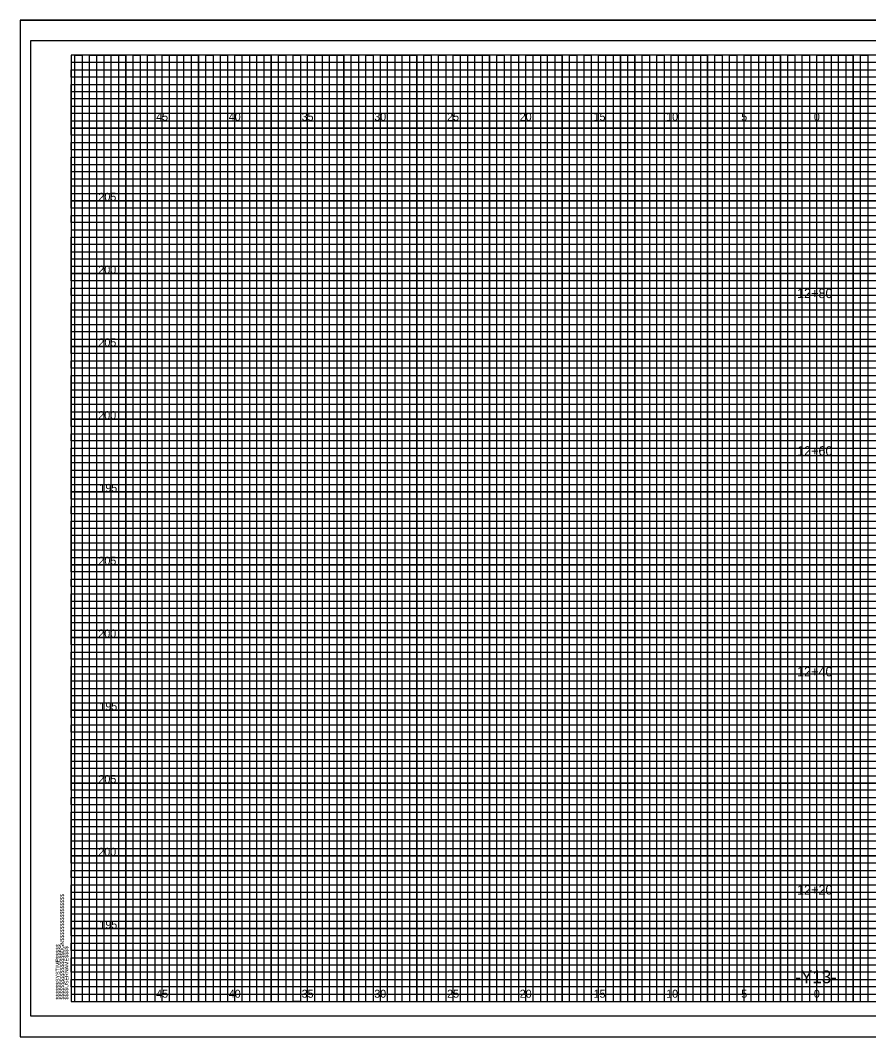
# Model space of a CAD drawing. Extents: x -4 to 103, y -2 to 209.
# Drawn here: x -3.5 to 54.8, y 68.4 to 138.2 of the extents above; entities that cross this region are included whole.
import ezdxf

# ---------------------------------------------------------------- set-up
doc = ezdxf.new("R2010")
doc.units = 0
for name, color, linetype in [('Exist XS Ground Line', 7, 'Continuous'), ('Old_Level_10', 7, 'Continuous'), ('Old_Level_16', 7, 'Continuous'), ('Old_Level_3', 7, 'Continuous'), ('Old_Level_5', 7, 'Continuous'), ('Old_Level_8', 7, 'Continuous'), ('Prop XS Finish Grade Earthwork', 7, 'Continuous'), ('Prop XS Finish Grade Pavement', 7, 'Continuous'), ('Prop XS Pvmt Edge Slope', 7, 'Continuous'), ('Prop XS SE Text', 7, 'Continuous'), ('Prop XS Suitable Common Exc Shape', 7, 'Continuous')]:
    doc.layers.add(name, color=color, linetype=linetype)

msp = doc.modelspace()

# ---------------------------------------------------------------- linework, layer by layer
at = {"layer": 'Exist XS Ground Line'}
msp.add_lwpolyline([(103, 136.825), (-2.8, 136.825), (-2.8, 69.825), (103, 69.825)], close=True, dxfattribs=at)
at = {"layer": 'Old_Level_10'}
for p, q in [((1.25, 70.825), (1.25, 135.825)), ((3.75, 70.825), (3.75, 135.825)), ((6.25, 70.825), (6.25, 135.825)), ((8.75, 70.825), (8.75, 135.825)), ((11.25, 70.825), (11.25, 135.825)), ((13.75, 70.825), (13.75, 135.825)), ((16.25, 70.825), (16.25, 135.825)), ((18.75, 70.825), (18.75, 135.825)), ((21.25, 70.825), (21.25, 135.825)), ((23.75, 70.825), (23.75, 135.825)), ((26.25, 70.825), (26.25, 135.825)), ((28.75, 70.825), (28.75, 135.825)), ((31.25, 70.825), (31.25, 135.825)), ((33.75, 70.825), (33.75, 135.825)), ((36.25, 70.825), (36.25, 135.825)), ((38.75, 70.825), (38.75, 135.825)), ((41.25, 70.825), (41.25, 135.825)), ((43.75, 70.825), (43.75, 135.825)), ((46.25, 70.825), (46.25, 135.825)), ((48.75, 70.825), (48.75, 135.825)), ((51.25, 70.825), (51.25, 135.825)), ((53.75, 70.825), (53.75, 135.825)), ((0, 133.325), (74.25, 133.325)), ((0, 130.825), (102.5, 130.825)), ((0, 128.325), (102.5, 128.325)), ((0, 125.825), (102.5, 125.825)), ((0, 123.325), (102.5, 123.325)), ((0, 120.825), (102.5, 120.825)), ((0, 118.325), (102.5, 118.325)), ((0, 115.825), (102.5, 115.825)), ((0, 113.325), (102.5, 113.325)), ((0, 110.825), (102.5, 110.825)), ((0, 108.325), (102.5, 108.325)), ((0, 105.825), (102.5, 105.825)), ((0, 103.325), (102.5, 103.325)), ((0, 100.825), (102.5, 100.825)), ((0, 98.325), (102.5, 98.325)), ((0, 95.825), (102.5, 95.825)), ((0, 93.325), (102.5, 93.325)), ((0, 90.825), (102.5, 90.825)), ((0, 88.325), (102.5, 88.325)), ((0, 85.825), (102.5, 85.825)), ((0, 83.325), (102.5, 83.325)), ((0, 80.825), (102.5, 80.825)), ((0, 78.325), (102.5, 78.325)), ((0, 75.825), (102.5, 75.825)), ((0, 73.325), (102.5, 73.325))]:
    msp.add_line(p, q, dxfattribs=at)
at = {"layer": 'Old_Level_3'}
for p, q in [((-3.5, 138.225), (103.4, 138.225)), ((-3.5, 138.225), (-3.5, 68.4)), ((-3.5, 68.4), (103.4, 68.4))]:
    msp.add_line(p, q, dxfattribs=at)
at = {"layer": 'Old_Level_5'}
msp.add_lwpolyline([(103.4, 138.225), (-3.5, 138.225), (-3.5, 68.4), (103.4, 68.4)], close=True, dxfattribs=at)
at = {"layer": 'Old_Level_8'}
for points in [[(1.25, 70.825), (1.25, 135.825), (3.75, 135.825), (3.75, 70.825), (6.25, 70.825), (6.25, 135.825), (8.75, 135.825), (8.75, 70.825), (11.25, 70.825), (11.25, 135.825), (13.75, 135.825), (13.75, 70.825), (16.25, 70.825), (16.25, 135.825), (18.75, 135.825), (18.75, 70.825), (21.25, 70.825), (21.25, 135.825), (23.75, 135.825), (23.75, 70.825), (26.25, 70.825), (26.25, 135.825), (28.75, 135.825), (28.75, 70.825), (31.25, 70.825), (31.25, 135.825), (33.75, 135.825), (33.75, 70.825), (36.25, 70.825), (36.25, 135.825), (38.75, 135.825), (38.75, 70.825), (41.25, 70.825), (41.25, 135.825), (43.75, 135.825), (43.75, 70.825), (46.25, 70.825), (46.25, 135.825), (48.75, 135.825), (48.75, 70.825), (51.25, 70.825), (51.25, 135.825), (53.75, 135.825), (53.75, 70.825)], [(102.5, 130.825), (0, 130.825), (0, 133.325), (74.25, 133.325)], [(102.5, 125.825), (0, 125.825), (0, 128.325), (102.5, 128.325)], [(102.5, 120.825), (0, 120.825), (0, 123.325), (102.5, 123.325)], [(102.5, 115.825), (0, 115.825), (0, 118.325), (102.5, 118.325)], [(102.5, 110.825), (0, 110.825), (0, 113.325), (102.5, 113.325)], [(102.5, 105.825), (0, 105.825), (0, 108.325), (102.5, 108.325)], [(102.5, 100.825), (0, 100.825), (0, 103.325), (102.5, 103.325)], [(102.5, 95.825), (0, 95.825), (0, 98.325), (102.5, 98.325)], [(102.5, 90.825), (0, 90.825), (0, 93.325), (102.5, 93.325)], [(102.5, 85.825), (0, 85.825), (0, 88.325), (102.5, 88.325)], [(102.5, 80.825), (0, 80.825), (0, 83.325), (102.5, 83.325)], [(102.5, 75.825), (0, 75.825), (0, 78.325), (102.5, 78.325)], [(0, 73.325), (102.5, 73.325)]]:
    msp.add_lwpolyline(points, dxfattribs=at)
at = {"layer": 'Prop XS Finish Grade Earthwork'}
for points in [[(0.25, 70.825), (0.25, 135.825), (0.75, 135.825), (0.75, 70.825), (1.75, 70.825), (1.75, 135.825), (2.25, 135.825), (2.25, 70.825), (2.75, 70.825), (2.75, 135.825), (3.25, 135.825), (3.25, 70.825), (4.25, 70.825), (4.25, 135.825), (4.75, 135.825), (4.75, 70.825), (5.25, 70.825), (5.25, 135.825), (5.75, 135.825), (5.75, 70.825), (6.75, 70.825), (6.75, 135.825), (7.25, 135.825), (7.25, 70.825), (7.75, 70.825), (7.75, 135.825), (8.25, 135.825), (8.25, 70.825), (9.25, 70.825), (9.25, 135.825), (9.75, 135.825), (9.75, 70.825), (10.25, 70.825), (10.25, 135.825), (10.75, 135.825), (10.75, 70.825), (11.75, 70.825), (11.75, 135.825), (12.25, 135.825), (12.25, 70.825), (12.75, 70.825), (12.75, 135.825), (13.25, 135.825), (13.25, 70.825), (14.25, 70.825), (14.25, 135.825), (14.75, 135.825), (14.75, 70.825), (15.75, 70.825), (15.25, 70.825), (15.25, 135.825), (15.75, 135.825), (15.75, 70.825), (16.75, 70.825), (16.75, 135.825), (17.25, 135.825), (17.25, 70.825), (17.75, 70.825), (17.75, 135.825), (18.25, 135.825), (18.25, 70.825), (19.25, 70.825), (19.25, 135.825), (19.75, 135.825), (19.75, 70.825), (20.25, 70.825), (20.25, 135.825), (20.75, 135.825), (20.75, 70.825), (21.75, 70.825), (21.75, 135.825), (22.25, 135.825), (22.25, 70.825), (22.75, 70.825), (22.75, 135.825), (23.25, 135.825), (23.25, 70.825), (24.25, 70.825), (24.25, 135.825), (24.75, 135.825), (24.75, 70.825), (25.25, 70.825), (25.25, 135.825), (25.75, 135.825), (25.75, 70.825), (26.75, 70.825), (26.75, 135.825), (27.25, 135.825), (27.25, 70.825), (27.75, 70.825), (27.75, 135.825), (28.25, 135.825), (28.25, 70.825), (29.25, 70.825), (29.25, 135.825), (29.75, 135.825), (29.75, 70.825), (30.25, 70.825), (30.25, 135.825), (30.75, 135.825), (30.75, 70.825)], [(30.75, 70.825), (31.75, 70.825), (31.75, 135.825), (32.25, 135.825), (32.25, 70.825), (32.75, 70.825), (32.75, 135.825), (33.25, 135.825), (33.25, 70.825), (34.25, 70.825), (34.25, 135.825), (34.75, 135.825), (34.75, 70.825), (35.25, 70.825), (35.25, 135.825), (35.75, 135.825), (35.75, 70.825), (36.75, 70.825), (36.75, 135.825), (37.25, 135.825), (37.25, 70.825), (37.75, 70.825), (37.75, 135.825), (37.75, 70.825)], [(38.25, 135.825), (38.25, 70.825), (39.25, 70.825), (39.25, 135.825), (39.75, 135.825), (39.75, 70.825), (40.25, 70.825), (40.25, 135.825), (40.75, 135.825), (40.75, 70.825), (41.75, 70.825), (41.75, 135.825), (42.25, 135.825), (42.25, 70.825), (42.75, 70.825), (42.75, 135.825), (43.25, 135.825), (43.25, 70.825), (43.75, 70.825), (44.25, 70.825), (44.25, 135.825), (44.75, 135.825), (44.75, 70.825), (45.25, 70.825), (45.25, 135.825), (45.75, 135.825), (45.75, 70.825), (46.75, 70.825), (46.75, 135.825), (47.25, 135.825), (47.25, 70.825), (47.75, 70.825), (47.75, 135.825), (48.25, 135.825), (48.25, 70.825), (49.25, 70.825), (49.25, 135.825), (49.75, 135.825), (49.75, 70.825), (50.25, 70.825), (50.25, 135.825), (50.75, 135.825), (50.75, 70.825), (51.75, 70.825), (51.75, 135.825), (52.25, 135.825), (52.25, 70.825), (52.75, 70.825), (52.75, 135.825), (53.25, 135.825), (53.25, 70.825), (54.25, 70.825), (54.25, 135.825), (54.75, 135.825), (54.75, 70.825), (55.25, 70.825)], [(0, 132.825), (0, 133.825), (74.25, 133.825), (74.25, 134.325), (0, 134.325), (0, 134.825), (74.25, 134.825), (74.25, 135.325), (0, 135.325)], [(102.5, 132.825), (0, 132.825)], [(102.5, 131.825), (0, 131.825), (0, 132.325), (102.5, 132.325)], [(102.5, 130.325), (0, 130.325), (0, 131.325), (102.5, 131.325)], [(102.5, 129.325), (0, 129.325), (0, 129.825), (102.5, 129.825)], [(102.5, 127.825), (0, 127.825), (0, 128.825), (102.5, 128.825)], [(102.5, 126.825), (0, 126.825), (0, 127.325), (102.5, 127.325)], [(102.5, 125.325), (0, 125.325), (0, 126.325), (102.5, 126.325)], [(102.5, 124.325), (0, 124.325), (0, 124.825), (102.5, 124.825)], [(0, 123.825), (102.5, 123.825)], [(102.5, 122.825), (0, 122.825)], [(102.5, 121.825), (0, 121.825), (0, 122.325), (102.5, 122.325)], [(102.5, 120.325), (0, 120.325), (0, 121.325), (102.5, 121.325)], [(102.5, 119.325), (0, 119.325), (0, 119.825), (102.5, 119.825)], [(102.5, 117.825), (0, 117.825), (0, 118.825), (102.5, 118.825)], [(102.5, 116.825), (0, 116.825), (0, 117.325), (102.5, 117.325)], [(102.5, 115.325), (0, 115.325), (0, 116.325), (102.5, 116.325)], [(102.5, 114.325), (0, 114.325), (0, 114.825), (102.5, 114.825)], [(102.5, 112.825), (0, 112.825), (0, 113.825), (102.5, 113.825)], [(102.5, 111.825), (0, 111.825), (0, 112.325), (102.5, 112.325)], [(102.5, 110.325), (0, 110.325), (0, 111.325), (102.5, 111.325)], [(102.5, 109.325), (0, 109.325), (0, 109.825), (102.5, 109.825)], [(102.5, 107.825), (0, 107.825), (0, 108.825), (102.5, 108.825)], [(102.5, 106.825), (0, 106.825), (0, 107.325), (102.5, 107.325)], [(102.5, 105.325), (0, 105.325), (0, 106.325), (102.5, 106.325)], [(102.5, 104.325), (0, 104.325), (0, 104.825), (102.5, 104.825)], [(102.5, 102.825), (0, 102.825), (0, 103.825), (102.5, 103.825)], [(102.5, 101.825), (0, 101.825), (0, 102.325)], [(0, 102.325), (102.5, 102.325)], [(102.5, 100.325), (0, 100.325), (0, 101.325), (102.5, 101.325)], [(102.5, 99.325), (0, 99.325), (0, 99.825), (102.5, 99.825)], [(102.5, 97.825), (0, 97.825), (0, 98.825), (102.5, 98.825)], [(102.5, 96.825), (0, 96.825), (0, 97.325), (102.5, 97.325)], [(102.5, 95.325), (0, 95.325), (0, 96.325), (102.5, 96.325)], [(102.5, 94.325), (0, 94.325), (0, 94.825), (102.5, 94.825)], [(102.5, 92.825), (0, 92.825), (0, 93.825), (102.5, 93.825)], [(102.5, 91.825), (0, 91.825), (0, 92.325), (102.5, 92.325)], [(102.5, 90.325), (0, 90.325), (0, 91.325), (102.5, 91.325)], [(102.5, 89.325), (0, 89.325), (0, 89.825), (102.5, 89.825)], [(102.5, 87.825), (0, 87.825), (0, 88.825), (102.5, 88.825)], [(102.5, 86.825), (0, 86.825), (0, 87.325), (102.5, 87.325)], [(102.5, 85.325), (0, 85.325), (0, 86.325), (102.5, 86.325)], [(102.5, 84.325), (0, 84.325), (0, 84.825), (102.5, 84.825)], [(102.5, 82.825), (0, 82.825), (0, 83.825), (102.5, 83.825)], [(102.5, 81.825), (0, 81.825), (0, 82.325), (102.5, 82.325)], [(102.5, 80.325), (0, 80.325), (0, 81.325), (102.5, 81.325)], [(102.5, 79.325), (0, 79.325), (0, 79.825), (102.5, 79.825)], [(102.5, 77.825), (0, 77.825), (0, 78.825), (102.5, 78.825)], [(102.5, 76.825), (0, 76.825), (0, 77.325), (102.5, 77.325)], [(102.5, 75.325), (0, 75.325), (0, 76.325), (102.5, 76.325)], [(102.5, 74.325), (0, 74.325), (0, 74.825), (102.5, 74.825)], [(102.5, 72.825), (0, 72.825), (0, 73.825), (102.5, 73.825)], [(102.5, 71.825), (0, 71.825), (0, 72.325), (102.5, 72.325)], [(0, 71.325), (102.5, 71.325)]]:
    msp.add_lwpolyline(points, dxfattribs=at)
at = {"layer": 'Prop XS SE Text'}
msp.add_lwpolyline([(102.5, 135.825), (0, 135.825), (0, 70.825), (102.5, 70.825)], close=True, dxfattribs=at)

# ---------------------------------------------------------------- texts
at = {"layer": 'Old_Level_16'}
for s, p in [('45', (5.84, 131.325)), ('40', (10.831, 131.325)), ('35', (15.84, 131.325)), ('30', (20.831, 131.325)), ('25', (25.84, 131.325)), ('20', (30.831, 131.325)), ('15', (35.906, 131.325)), ('10', (40.897, 131.325)), ('5', (46.057, 131.325)), ('0', (51.049, 131.325)), ('0', (51.049, 131.325)), ('45', (5.84, 71.075)), ('40', (10.831, 71.075)), ('35', (15.84, 71.075)), ('30', (20.831, 71.075)), ('25', (25.84, 71.075)), ('20', (30.831, 71.075)), ('15', (35.906, 71.075)), ('10', (40.897, 71.075)), ('5', (46.057, 71.075)), ('0', (51.049, 71.075)), ('0', (51.049, 71.075))]:
    msp.add_text(s, height=0.55, dxfattribs=at).set_placement(p)
at = {"layer": 'Old_Level_8'}
msp.add_text('040397', height=0.0025, rotation=90, dxfattribs=at).set_placement((-0.001, 135.811))
at = {"layer": 'Prop XS Finish Grade Pavement'}
for s, p in [('205', (1.872, 125.825)), ('200', (1.864, 120.825)), ('205', (1.872, 115.825)), ('200', (1.864, 110.825)), ('195', (1.938, 105.825)), ('205', (1.872, 100.825)), ('200', (1.864, 95.825)), ('195', (1.938, 90.825)), ('205', (1.872, 85.825)), ('200', (1.864, 80.825)), ('195', (1.938, 75.825))]:
    msp.add_text(s, height=0.55, dxfattribs=at).set_placement(p)
at = {"layer": 'Prop XS Pvmt Edge Slope'}
msp.add_text('-Y13-', height=0.875, dxfattribs=at).set_placement((49.773, 72.075))
at = {"layer": 'Prop XS SE Text'}
for s, p in [('$$$$$$$$$$$$$$$$DGN$$$$$$$$$$$$$$$$', (-0.5, 70.95)), ('$$$$$$SYSTIME$$$$$', (-0.797, 70.95)), ('$$$$USERNAME$$$$', (-0.2, 70.95))]:
    msp.add_text(s, height=0.2625, rotation=90, dxfattribs=at).set_placement(p)
at = {"layer": 'Prop XS Suitable Common Exc Shape'}
for s, p in [('12+80', (49.893, 119.142)), ('12+60', (49.893, 108.315)), ('12+40', (49.893, 93.153)), ('12+20', (49.893, 78.165))]:
    msp.add_text(s, height=0.65, dxfattribs=at).set_placement(p)

doc.saveas('drawing.dxf')
